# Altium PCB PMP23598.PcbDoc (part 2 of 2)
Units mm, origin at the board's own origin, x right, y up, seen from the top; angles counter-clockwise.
Board outline 80 x 60 mm, 4 copper layers (Top Layer, Layer 1, Layer 2, Bottom Layer), stack 1.856 mm thick; 92 components, 46 nets, 417 pads, 121 vias.
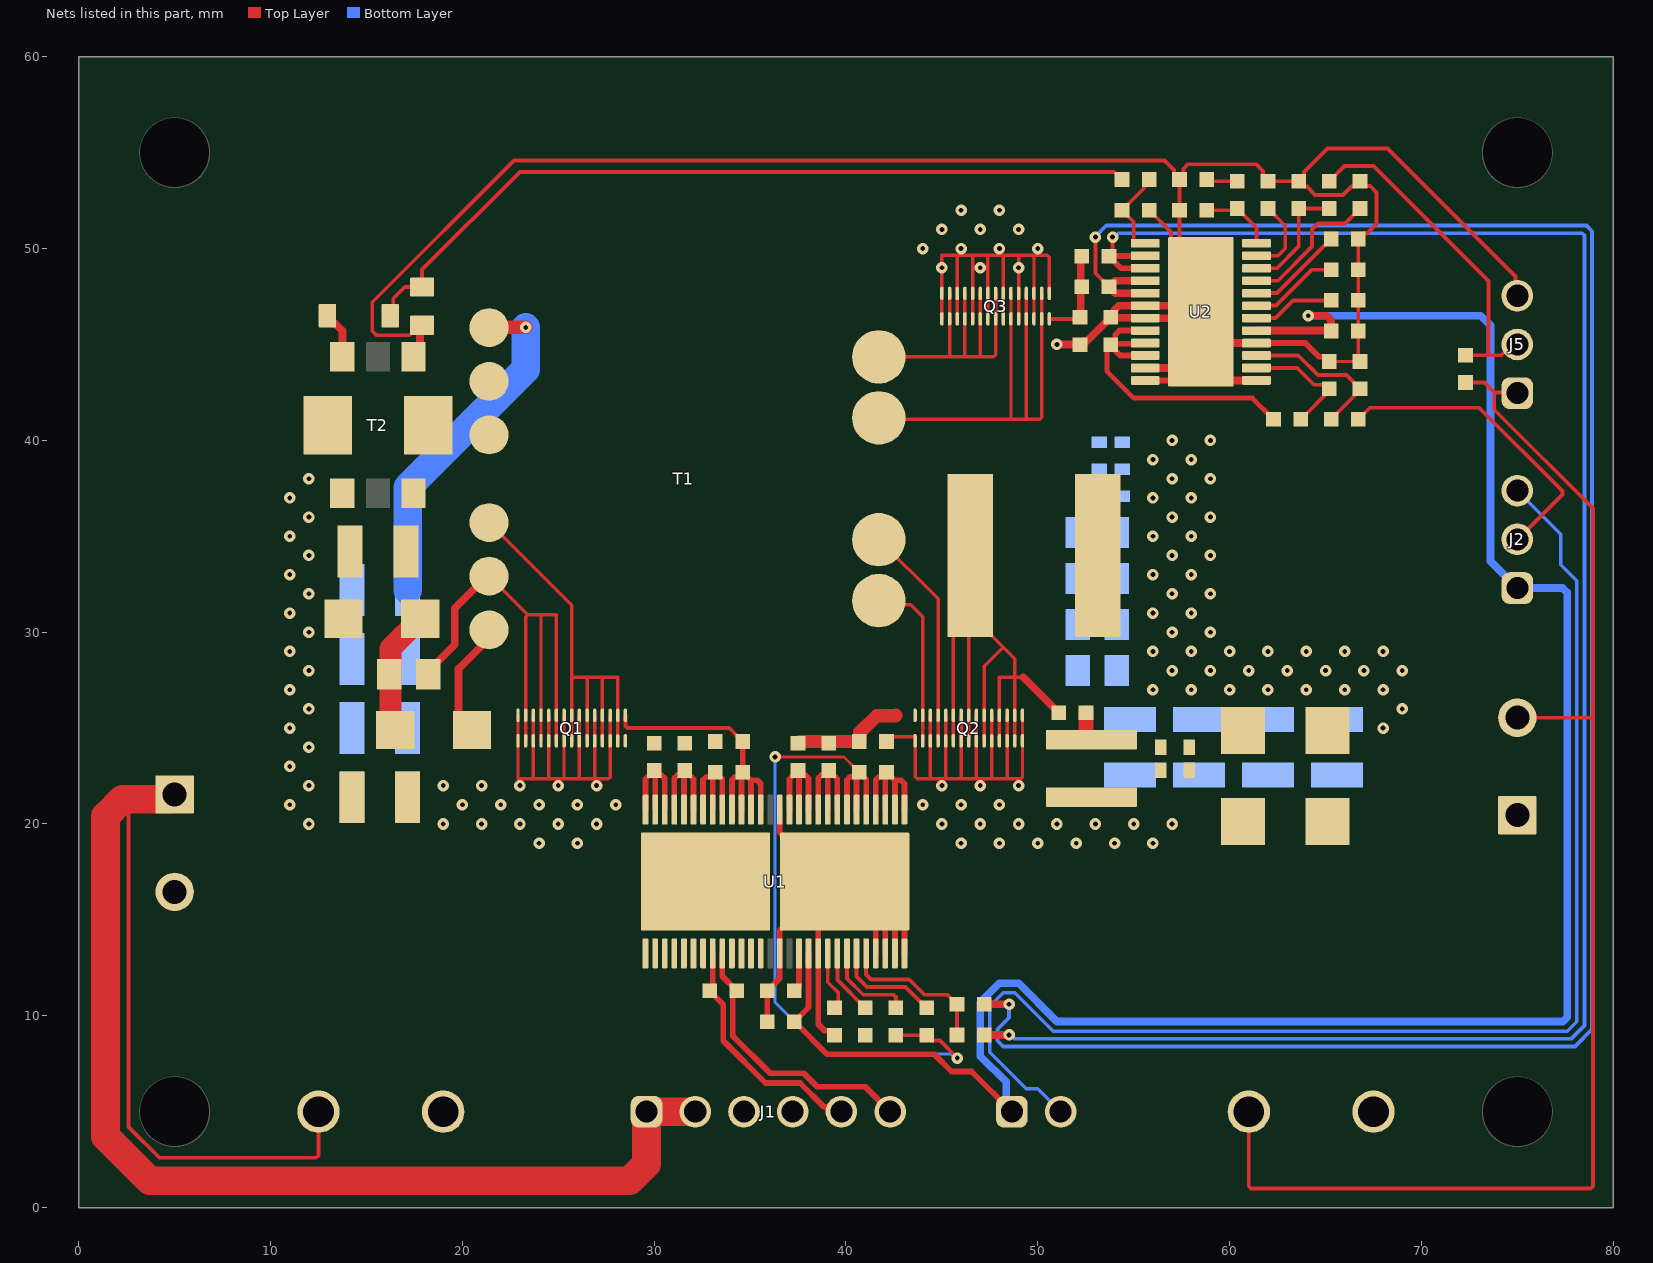
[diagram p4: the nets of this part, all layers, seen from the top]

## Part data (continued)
TP2 TP4: library part CMP-0055148-2, "Test Point, Multipurpose, Black, TH", Color=Black, Manufacturer="Keystone Electronics", Supplier Part Number 1=36-5011-ND
U1: library part CMP-0120202-4, Manufacturer="Texas Instruments", Operating Temperature Range=to
U2: library part CMP-0122233-2, "Radiation-Hardness-Assured 1-MHz Current Mode PWM Controller with Integrated Gate Driver", Manufacturer="Texas Instruments", Max Supply Voltage=14V, Min Supply Voltage=4.5V, Nominal Supply Current=5-22mA, Operating Temperature Range="-55°C to +125°C"

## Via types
v1: diameter 0.6, hole 0.25, Top Layer to Bottom Layer, 121 vias

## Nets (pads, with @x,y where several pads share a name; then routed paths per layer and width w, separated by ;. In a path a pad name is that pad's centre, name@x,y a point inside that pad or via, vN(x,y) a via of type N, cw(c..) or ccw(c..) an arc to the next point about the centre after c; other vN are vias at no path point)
+12Vp: C10.1 J1.5 U1.8 | length 12.6
  Top Layer w0.3: U1.8@33.05,13.25 33.05,11.461 C10.1@32.889,11.3 33.6,10.589 33.6,8.7 35.8,6.5 37.6,6.5 38.842,5.258 39.502,5.258 J1.5@39.76,5
+12Vs: C1.1 C2.1 J2.1 J3.1 U1.18 U2.17 | length 110
  Top Layer w0.3: U1.18@38.05,13.25 38.05,10.439 C1.1@37.311,9.7 39.011,8 44.6,8 45.5,7.1 46.55,7.1 J3.1@48.65,5
  Top Layer w0.4: U2.17@61.4,45.725 C2.1@65.264,45.725 ; v1(64.1,46.5) 65.054,46.5 65.289,46.266 C2.1@65.289,45.7
  Bottom Layer w0.4: J3.1@48.65,5 48.347,5.303 48.347,6.553 47,7.9 47,10.7 48,11.7 49,11.7 51,9.7 77.366,9.7 77.6,9.934 77.6,32.066 77.366,32.3 J2.1@75,32.3 73.6,33.7 73.6,46 73.1,46.5 v1(64.1,46.5)
BP5L: C8.2 R5.2 R8.1 U1.33 U1.34 U1.35 | length 37.8
  Top Layer w0.152: v1(36.3,23.5) 39.889,23.5 C8.2@40.689,22.7
  Top Layer w0.2: R8.1@42.6,8.989 R5.2@44.2,8.989 44.481,8.708 44.892,8.708 v1(45.8,7.8)
  Top Layer w0.3: U1.35@40.05,20.75 40.05,22.293 40.226,22.469 C8.2@40.458,22.469 ; U1.34@40.55,20.75 C8.2@40.55,22.561 ; C8.2@40.689,22.7 41.05,22.339 U1.33@41.05,20.75
  Bottom Layer w0.152: v1(36.3,23.5) 36.3,10.711 39.011,8 45.482,8 45.682,7.8 v1(45.8,7.8)
CS: D3.1 R18.2 R30.2 | length 42.4
  Top Layer w0.2: D3.1@16.235,46.5 16.393,46.658 16.393,47.393 16.992,47.992 17.892,47.992 R30.2@17.9,48 17.9,48.9 23,54 53.989,54 R18.2@54.389,53.6
NetC3_2: C3.2 U1.17 | length 2
  Top Layer w0.2: C3.2@37.311,11.3 C3.2@37.55,11.539
  Top Layer w0.3: C3.2@37.55,11.539 U1.17@37.55,13.25
NetC4_1: C4.1 R1.2 U2.8 U2.9 U2.10 | length 17.4
  Top Layer w0.254: C4.1@53.8,44.989 53.6,44.789 53.6,43.6 55,42.2 61.189,42.2 R1.2@62.289,41.1
  Top Layer w0.3: U2.10@55.6,44.425 54.3,44.425 54.031,44.694 54.031,44.758 C4.1@53.8,44.989 ; U2.9@55.6,45.075 55.557,45.032 53.843,45.032 C4.1@53.8,44.989 ; U2.8@55.6,45.725 54.261,45.725 54.031,45.495 54.031,45.22 C4.1@53.8,44.989
NetC5_2: C5.2 U2.21 | length 7.5
  Top Layer w0.2: U2.21@61.4,48.325 62.525,48.325 64.3,50.1 64.3,51 64.6,51.3 66.011,51.3 C5.2@66.8,52.089
NetC6_1: C6.1 U2.20 | length 5.1
  Top Layer w0.2: U2.20@61.4,47.675 62.464,47.675 C6.1@65.289,50.5
NetC7_2: C7.2 U1.48 U1.49 U1.50 | length 5.9
  Top Layer w0.3: U1.50@32.55,20.75 32.55,22.293 32.726,22.469 C7.2@32.958,22.469 ; U1.49@33.05,20.75 C7.2@33.05,22.561 ; C7.2@33.189,22.7 33.55,22.339 U1.48@33.55,20.75
NetC9_1: C9.1 R14.2 | length 1.6
  Top Layer w0.2: C9.1@58.811,53.6 58.9,53.511 R14.2@60.4,53.511
NetC11_2: C11.2 R14.1 U2.24 | length 3.9
  Top Layer w0.2: C11.2@58.811,52 60.311,52 R14.1@60.4,52.089 61.4,51.089 U2.24@61.4,50.275
NetC15_1: C15.1 R18.1 U2.1 | length 4.7
  Top Layer w0.2: U2.1@55.6,50.275 55.125,50.275 55,50.4 55,51.389 C15.1@54.389,52 55.53,53.141 55.53,53.319 R18.1@55.811,53.6
NetC17_1: C17.1 D1.2 D2.1 | length 6.6
  Top Layer w1.143: D2.1@16.5,24.9 16.248,25.152 16.248,27.737 C17.1@16.184,27.8 16.248,27.864 16.248,29.148 D1.2@17.8,30.7
NetC17_2: C17.2 Q1.3 Q1.4 Q1.7 Q1.8 Q1.11 Q1.12 Q1.15 Q1.16 Q1.19 Q1.20 Q1.23 Q1.24 Q1.27 Q1.28 T1.4 T1.5 | length 56.1
  Top Layer w0.178: T1.5@21.39,32.92 23.41,30.9 ; T1.4@21.39,35.715 25.7,31.405 25.7,27.546 ; Q1.27@23.3,24.335 Q1.28@23.3,25.665 23.3,30.796 23.306,30.796 23.41,30.9 ; Q1.23@24.1,24.335 Q1.24@24.1,25.665 24.1,30.9 ; Q1.19@24.9,24.335 Q1.20@24.9,25.665 24.9,30.9 23.41,30.9 ; Q1.15@25.7,24.335 Q1.16@25.7,25.665 25.7,27.546 ; Q1.11@26.5,24.335 Q1.12@26.5,25.665 26.5,27.65 ; Q1.7@27.3,24.335 27.3,27.65 ; Q1.3@28.1,24.335 Q1.4@28.1,25.665 28.1,27.65 27.3,27.65 ; 25.7,27.546 25.804,27.65 26.5,27.65 ; 26.5,27.65 27.3,27.65
  Top Layer w0.4: C17.2@18.216,27.8 18.216,27.965 19.6,29.349 19.6,31.249 21.271,32.92 T1.5@21.39,32.92
NetC19_1: C19.1 L1.1 Q2.3 Q2.4 Q2.7 Q2.8 Q2.11 Q2.12 Q2.15 Q2.16 Q2.19 Q2.20 Q2.23 Q2.24 Q2.27 Q2.28 T1.7 T1.8 | length 60.2
  Top Layer w0.178: T1.7@41.71,31.65 41.936,31.424 43.372,31.424 44,30.796 Q2.3@44,25.665 Q2.4@44,24.335 ; T1.8@41.71,34.825 44.8,31.735 Q2.7@44.8,25.665 Q2.8@44.8,24.335 ; Q2.12@45.6,24.335 L1.1@45.6,30.9 ; Q2.16@46.4,24.335 Q2.15@46.4,25.665 46.4,33.925 L1.1@46.475,34 46.475,30.94 48.2,29.215 ; Q2.20@47.2,24.335 Q2.19@47.2,25.665 47.2,28.215 48.2,29.215 ; Q2.24@48,24.335 Q2.23@48,25.665 48,27.65 49.239,27.65 ; Q2.28@48.8,24.335 Q2.27@48.8,25.665 48.8,28.615 48.2,29.215
  Top Layer w0.4: 49.239,27.65 C19.1@51.089,25.8
NetC19_2: C19.2 R29.2 | length 1.6
  Top Layer w0.762: C19.2@52.511,25.8 52.511,24.526 52.638,24.399 R29.2@52.8,24.399
NetD2_2: D2.2 T1.6 | length 6.2
  Top Layer w0.4: D2.2@20.5,24.9 19.8,25.6 19.8,28.094 21.39,29.684 T1.6@21.39,30.125
NetD3_2: D3.2 T2.3 | length 2.6
  Top Layer w0.4: D3.2@12.965,46.5 12.965,46.345 13.22,46.09 13.374,46.09 13.746,45.718 T2.3@13.746,44.356
NetJ2_2: J2.2 R3.2 | length 16.2
  Top Layer w0.2: R3.2@66.711,41.1 67.311,41.7 73,41.7 77.347,37.353 77.347,37.187 J2.2@75,34.84
NetJ5_2: J5.2 R22.2 R25.1 | length 17.9
  Top Layer w0.2: R22.2@65.2,53.511 65.989,54.3 67.5,54.3 73.5,48.3 73.5,44.441 ; R25.1@72.3,44.441 73.5,44.441 ; J5.2@75,45 74.717,45 74.158,44.441 73.5,44.441
NetQ1_1: Q1.1 R15.2 R16.2 R17.1
NetQ2_1: Q2.1 R20.2 R21.2 R24.1 | length 6
  Top Layer w0.7: R21.2@37.5,24.211 37.589,24.3 39.1,24.3 R24.1@40.689,24.3 40.72,24.331 40.72,24.772 41.598,25.65 42.585,25.65 42.6,25.665
NetQ3_1: Q3.1 R26.1 R27.1 R28.2 | length 4.9
  Top Layer w0.2: Q3.1@50.6,46.335 52.124,46.335 R28.2@52.2,46.411
  Top Layer w0.4: R28.2@52.2,46.411 52.244,46.456 52.244,49.556 R26.1@52.289,49.6
NetQ3_3: Q3.3 Q3.4 Q3.7 Q3.8 Q3.11 Q3.12 Q3.15 Q3.16 Q3.19 Q3.20 Q3.23 Q3.24 Q3.27 Q3.28 T1.10 T1.11 | length 47.4
  Top Layer w0.178: T1.10@41.71,41.175 41.785,41.1 48.6,41.1 ; T1.11@41.71,44.35 45.4,44.35 ; Q3.28@45.4,47.665 45.4,44.35 ; Q3.24@46.2,47.665 Q3.23@46.2,46.335 46.2,44.35 ; Q3.20@47,47.665 Q3.19@47,46.335 47,44.35 ; Q3.16@47.8,47.665 Q3.15@47.8,46.335 47.8,44.454 47.696,44.35 47,44.35 ; Q3.12@48.6,47.665 48.6,41.1 ; Q3.8@49.4,47.665 Q3.7@49.4,46.335 49.4,41.1 ; Q3.4@50.2,47.665 Q3.3@50.2,46.335 50.2,41.204 50.096,41.1 49.4,41.1 ; 45.4,44.35 46.2,44.35 ; 46.2,44.35 47,44.35 ; 48.6,41.1 49.4,41.1
NetR1_1: R1.1 R2.1 U2.14 | length 6.5
  Top Layer w0.2: U2.14@61.4,43.775 63.525,43.775 64.397,42.903 64.986,42.903 R2.1@65.2,42.689 64.919,42.408 64.919,42.308 63.992,41.381 R1.1@63.711,41.1
NetR3_1: R3.1 R9.2 U2.15 | length 8.3
  Top Layer w0.2: U2.15@61.4,44.425 63.575,44.425 64.6,43.4 66.089,43.4 R9.2@66.8,42.689 66.519,42.408 66.519,42.33 R3.1@65.289,41.1
NetR4_2: R4.2 U1.21 | length 3.4
  Top Layer w0.2: U1.21@39.55,13.25 39.55,11.861 R4.2@41,10.411
NetR5_1: R5.1 U1.23 | length 5.5
  Top Layer w0.2: U1.23@40.55,13.25 40.55,12.05 41.1,11.5 43.111,11.5 R5.1@44.2,10.411
NetR6_1: R6.1 R7.1 U1.24 | length 8.1
  Top Layer w0.2: U1.24@41.05,13.25 41.05,12.15 41.3,11.9 43.3,11.9 44.1,11.1 45.289,11.1 R7.1@45.789,10.6 R6.1@45.789,9
NetR8_2: R8.2 U1.22 | length 4.8
  Top Layer w0.2: U1.22@40.05,13.25 40.05,11.95 40.9,11.1 42.483,11.1 42.6,10.983 R8.2@42.6,10.411
NetR10_2: R10.2 U1.20 | length 3.1
  Top Layer w0.2: U1.20@39.05,13.25 39.05,11.75 39.6,11.2 39.6,10.611 R10.2@39.4,10.411
NetR11_2: R11.2 U2.18 | length 4.3
  Top Layer w0.2: U2.18@61.4,46.375 62.385,46.375 63.31,47.3 R11.2@65.289,47.3
NetR12_2: R12.2 U2.19 | length 4.7
  Top Layer w0.2: U2.19@61.4,47.025 62.425,47.025 64.3,48.9 R12.2@65.289,48.9
NetR13_2: R13.2 U2.23 | length 4.1
  Top Layer w0.2: U2.23@61.4,49.625 62.525,49.625 62.9,50 62.9,51.189 R13.2@62,52.089
NetR15_1: R15.1 U1.51 U1.52 U1.53 | length 6.5
  Top Layer w0.3: U1.53@31.05,20.75 31.05,22.382 31.226,22.558 31.369,22.558 31.55,22.739 U1.52@31.55,20.75 ; R15.1@31.6,22.789 32.05,22.339 U1.51@32.05,20.75
NetR16_1: R16.1 U1.54 U1.55 U1.56 | length 6.6
  Top Layer w0.3: U1.56@29.55,20.75 29.55,22.339 R16.1@30,22.789 ; U1.55@30.05,20.75 30.05,22.739 R16.1@30,22.789 ; U1.54@30.55,20.75 30.55,22.382 30.374,22.558 30.231,22.558 R16.1@30,22.789
NetR19_2: R19.2 R22.1 U2.22 | length 6.3
  Top Layer w0.2: U2.22@61.4,48.975 62.475,48.975 63.6,50.1 R19.2@63.6,52.089 R22.1@65.2,52.089
NetR20_1: R20.1 U1.36 U1.37 U1.38 | length 6.5
  Top Layer w0.3: U1.38@38.55,20.75 38.55,22.382 38.726,22.558 38.869,22.558 39.05,22.739 U1.37@39.05,20.75 ; R20.1@39.1,22.789 39.55,22.339 U1.36@39.55,20.75
NetR21_1: R21.1 U1.39 U1.40 U1.41 | length 6.6
  Top Layer w0.3: U1.41@37.05,20.75 37.05,22.339 R21.1@37.5,22.789 ; U1.40@37.55,20.75 37.55,22.739 R21.1@37.5,22.789 ; U1.39@38.05,20.75 38.05,22.382 37.874,22.558 37.731,22.558 R21.1@37.5,22.789
NetR23_1: R23.1 T1.2 T1.3 T2.6 T2.8
OUTH: R6.2 R26.2 U2.2 U2.3 | length 102.7
  Top Layer w0.2: R26.2@53.711,49.6 53.9,49.789 v1(53.9,50.6)
  Top Layer w0.3: U2.3@55.6,48.975 54.336,48.975 R26.2@53.711,49.6 53.724,49.612 55.587,49.612 U2.2@55.6,49.625
  Top Layer w0.4: R6.2@47.211,9 v1(48.5,9)
  Bottom Layer w0.2: v1(48.5,9) 48.611,9 48.811,8.8 77.8,8.8 78.5,9.5 78.5,50.683 78.383,50.8 54.211,50.8 54.011,50.6 v1(53.9,50.6)
OUTL: R7.2 R27.2 U2.4 U2.5 | length 109.8
  Top Layer w0.2: v1(53,50.6) 53,48.711 R27.2@53.711,48
  Top Layer w0.4: R7.2@47.211,10.6 v1(48.5,10.6) ; U2.5@55.6,47.675 54.036,47.675 R27.2@53.711,48 54.036,48.325 U2.4@55.6,48.325
  Bottom Layer w0.2: v1(48.5,10.6) 48.5,9.9 47.9,9.3 47.9,8.7 48.2,8.4 78,8.4 78.9,9.3 78.9,50.9 78.6,51.2 53.571,51.2 53,50.629 v1(53,50.6)
PGND: C7.1 C10.2 C12.2 C13.2 C14.2 C16.2 C18.2 J1.3 J1.4 J1.6 J4.2 Q1. Q1.2 Q1.5 Q1.6 Q1.9 Q1.10 Q1.13 Q1.14 Q1.17 Q1.18 Q1.21 Q1.22 Q1.25 Q1.26 Q1.30 R17.2 T1.1 TP2.1 U1.1 U1.2 U1.3 U1.4 U1.5 U1.6 U1.7 U1.9 U1.10 U1.11 U1.12 U1.13 U1.44 U1.45 U1.46 U1.47 U1.57 | length 77.5
  Top Layer w0.178: Q1.30@22.9,25.665 22.9,22.35 27.615,22.35 27.7,22.435 Q1.5@27.7,24.335 Q1.6@27.7,25.665 ; 23.7,22.35 Q1.25@23.7,24.335 Q1.26@23.7,25.665 ; 24.5,22.35 Q1.21@24.5,24.335 Q1.22@24.5,25.665 ; 25.3,22.454 Q1.17@25.3,24.335 Q1.18@25.3,25.665 ; 26.1,22.35 Q1.14@26.1,25.665 ; 26.9,22.35 Q1.9@26.9,24.335 Q1.10@26.9,25.665
  Top Layer w0.2: Q1.2@28.5,25.665 28.5,25.117 28.617,25 33.911,25 R17.2@34.611,24.3
  Top Layer w0.3: U1.9@33.55,13.25 33.55,12.061 C10.2@34.311,11.3 34.1,11.089 34.1,8.95 36.05,7 37.8,7 38.5,6.3 41,6.3 J1.6@42.3,5 ; U1.47@34.05,20.75 34.05,22.293 34.226,22.469 34.38,22.469 C7.1@34.611,22.7 ; U1.46@34.55,20.75 34.55,22.639 C7.1@34.611,22.7 ; R17.2@34.611,24.3 C7.1@34.611,22.7 ; U1.45@35.05,20.75 35.05,22.261 ; U1.44@35.55,20.75 35.55,22.1 35.374,22.276 35.126,22.276 35.111,22.261 35.05,22.261 ; C7.1@34.611,22.7 35.05,22.261
  Top Layer w0.7: T1.1@21.39,45.875 21.405,45.89 v1(23.3,45.89)
  Bottom Layer w1.5: C18.2@17.15,32.2 17.15,37.55 23.3,43.7 v1(23.3,45.89)
  other v1: 24,19 26,19 19,20 21,20 23,20 25,20 27,20 20,21 22,21 24,21 26,21 28,21 19,22 21,22 23,22 25,22 27,22
SGND: C1.2 C2.2 C3.1 C4.2 C5.1 C6.2 C8.1 C9.2 C11.1 C15.2 C20.1 C21.2 C22.1 C23.2 C24.1 C25.2 C26.1 C27.2 C28.2 C29.2 C30.2 C31.2 C32.2 C33.2 C34.2 J2.3 J3.2 J5.3 J6.1 Q2.2 Q2.5 Q2.6 Q2.9 Q2.10 Q2.13 Q2.14 Q2.17 Q2.18 Q2.21 Q2.22 Q2.25 Q2.26 Q2.29 Q2.30 Q3.2 Q3.5 Q3.6 Q3.9 Q3.10 Q3.13 Q3.14 Q3.17 Q3.18 Q3.21 Q3.22 Q3.25 Q3.26 Q3.29 Q3.30 R2.2 R4.1 R9.1 R10.1 R11.1 R12.1 R13.1 R19.1 R24.2 R28.1 R29.1 R30.1 T2.1 TP4.1 U1.15 U1.19 U1.25 U1.26 U1.27 U1.28 U1.29 U1.30 U1.31 U1.32 U1.42 U1.58 U2.6 U2.7 U2.11 U2.12 U2.13 U2.16 U2.25 | length 294.1
  Top Layer w0.178: R24.2@42.111,24.3 42.351,24.539 43.599,24.539 43.6,24.538 43.6,22.454 43.704,22.35 44.4,22.35 ; Q2.5@44.4,25.665 Q2.6@44.4,24.335 44.4,22.35 ; Q3.29@45,46.335 45,49.65 45.8,49.65 ; Q2.9@45.2,25.665 Q2.10@45.2,24.335 45.2,22.35 ; Q3.25@45.8,46.335 Q3.26@45.8,47.665 45.8,49.65 ; Q2.13@46,25.665 Q2.14@46,24.335 46,22.35 ; Q3.21@46.6,46.335 46.6,49.65 ; 46.8,22.454 Q2.17@46.8,25.665 ; Q3.17@47.4,46.335 47.4,49.546 ; Q2.21@47.6,25.665 47.6,22.35 ; Q3.13@48.2,46.335 Q3.14@48.2,47.665 48.2,49.65 ; Q2.25@48.4,25.665 Q2.26@48.4,24.335 48.4,22.35 ; Q3.9@49,46.335 Q3.10@49,47.665 49,49.65 ; Q2.29@49.2,25.665 49.2,22.435 49.115,22.35 48.4,22.35 ; Q3.5@49.8,46.335 Q3.6@49.8,47.665 49.8,49.65 ; Q3.2@50.6,47.665 50.6,49.546 50.496,49.65 49.8,49.65 ; R2.2@64.953,44.358 R2.2@65.2,44.111 R9.1@66.711,44.111 ; C6.2@66.711,50.5 C2.2@66.711,45.7 66.711,44.2 R9.1@66.8,44.111 ; 44.4,22.35 45.2,22.35 ; 45.2,22.35 46,22.35 ; 45.8,49.65 46.6,49.65 ; 46,22.35 47.6,22.35 ; 46.6,49.65 48.2,49.65 ; 47.6,22.35 48.4,22.35 ; 48.2,49.65 49,49.65 ; 49,49.65 49.8,49.65
  Top Layer w0.2: R30.1@17.79,45.89 17.665,45.89 17.257,45.482 15.518,45.482 15.3,45.7 15.3,47.2 22.7,54.6 56.6,54.6 57.108,54.092 57.108,53.881 C9.2@57.389,53.6 ; C15.2@55.811,52 56.94,50.871 56.94,50.511 57.151,50.3 57.3,50.3 57.389,50.389 C11.1@57.389,52 C9.2@57.389,53.6 ; C6.2@66.711,50.5 66.992,50.781 67.162,50.781 67.664,51.283 67.664,52.918 67.329,53.253 67.058,53.253 C5.1@66.8,53.511 66.519,53.23 66.35,53.23 65.92,52.8 64.457,52.8 64.027,53.23 63.881,53.23 R19.1@63.6,53.511 ; J5.3@75,47.54 74.897,47.643 74.897,48.548 68.227,55.218 65.104,55.218 63.881,53.995 63.881,53.792 R19.1@63.6,53.511 ; C9.2@57.389,53.6 57.597,53.808 57.597,54.164 57.833,54.4 61.371,54.4 61.737,54.034 61.737,53.775 R13.1@62,53.511 R19.1@63.6,53.511
  Top Layer w0.3: C1.2@35.889,9.7 C3.1@35.889,11.3 36.55,11.961 U1.15@36.55,13.25 36.55,14.45 37.4,15.3 U1.58@37.4,16.35 ; U1.42@36.55,20.75 36.55,19.55 37.15,18.95 U1.58@37.4,18.95 ; U1.58@38.5,15.05 38.55,15 U1.19@38.55,13.25 38.55,9.564 38.894,9.22 39.169,9.22 R10.1@39.4,8.989 ; U1.58@40.7,16.35 41.55,15.5 U1.25@41.55,13.25 ; U1.32@41.55,20.75 41.55,22.293 41.726,22.469 41.88,22.469 C8.1@42.111,22.7 ; U1.26@42.05,13.25 42.05,16.1 42.55,15.6 U1.27@42.55,13.25 ; U1.31@42.05,20.75 42.05,22.639 C8.1@42.111,22.7 ; U1.30@42.55,20.75 42.55,22.261 ; U1.58@42.9,15.05 43.05,14.9 U1.28@43.05,13.25 ; U1.29@43.05,20.75 43.05,22.1 42.874,22.276 42.626,22.276 42.611,22.261 42.55,22.261 ; U2.12@55.6,43.125 58.002,43.125 U2.25@58.04,43.163 ; U2.16@61.4,45.075 63.947,45.075 64.663,44.358 R2.2@64.953,44.358 ; C8.1@42.111,22.7 42.55,22.261
  Top Layer w0.4: T2.1@17.454,44.356 17.79,44.692 R30.1@17.79,45.89 ; v1(51,45) 51.006,44.994 52.194,44.994 R28.1@52.2,44.989 52.381,45.17 52.559,45.17 C4.2@53.8,46.411 53.981,46.592 53.981,46.791 54.215,47.025 U2.6@55.6,47.025 58.175,47.025 U2.25@58.5,46.7 ; C4.2@53.981,46.393 55.582,46.393 U2.7@55.6,46.375 58.455,46.375 U2.25@58.575,46.256 ; U2.11@55.6,43.775 57,43.775 58.5,45.275 58.5,44.625 60,43.125 U2.13@61.4,43.125 ; U2.25@58.697,46.378 60,45.075 U2.16@61.4,45.075
  Bottom Layer w0.178: J3.2@51.19,5 49.99,6.2 49.4,6.2 47.5,8.1 47.5,10.5 48.2,11.2 48.8,11.2 50.8,9.2 77.6,9.2 78.1,9.7 78.1,32.673 77.267,33.505 77.267,35.113 J2.3@75,37.38
  other v1: 46,19 48,19 50,19 52,19 54,19 56,19 45,20 47,20 49,20 51,20 53,20 55,20 57,20 44,21 46,21 48,21 45,22 47,22 49,22 45,49 47,49 49,49 44,50 46,50 48,50 50,50 45,51 47,51 49,51 46,52 48,52
VIN: C12.1 C13.1 C14.1 C16.1 C18.1 D1.1 J1.1 J1.2 J4.1 R23.2 T2.4 T2.7 TP1.1 | length 85.8
  Top Layer w0.2: 2.6,21.54 2.6,4.2 4.2,2.6 12.383,2.6 12.5,2.717 TP1.1@12.5,5
  Top Layer w1.5: J4.1@5,21.54 4.75,21.29 2.279,21.29 1.4,20.411 1.4,3.7 3.7,1.4 28.721,1.4 29.6,2.279 J1.1@29.6,5 J1.2@32.14,5
  other v1: 12,20 11,21 12,22 11,23 12,24 11,25 12,26 11,27 12,28 11,29 12,30 11,31 12,32 11,33 12,34 11,35 12,36 11,37 12,38
VOUT: C20.2 C21.1 C22.2 C23.1 C24.2 C25.1 C26.2 C27.1 C28.1 C29.1 C30.1 C31.1 C32.1 C33.1 C34.1 J5.1 J6.2 L1.2 R25.2 TP3.1 | length 72.3
  Top Layer w0.2: TP3.1@61,5 61,1.117 61.117,1 78.824,1 78.941,1.117 78.941,25.54 ; R25.2@72.3,43.019 73.281,43.019 73.8,42.5 ; J6.2@75,25.54 78.941,25.54 ; J5.1@75,42.46 74.96,42.5 73.8,42.5 ; 73.8,42.5 73.8,41.6 78.941,36.459 78.941,25.54
  other v1: 68,25 69,26 56,27 58,27 60,27 62,27 64,27 66,27 68,27 57,28 59,28 61,28 63,28 65,28 67,28 69,28 56,29 58,29 60,29 62,29 64,29 66,29 68,29 57,30 59,30 56,31 58,31 57,32 59,32 56,33 58,33 57,34 59,34 56,35 58,35 57,36 59,36 56,37 58,37 57,38 59,38 56,39 58,39 57,40 59,40
pads on no net: H1.0 H1.MH H2.0 H2.MH H3.0 H3.MH H4.0 H4.MH Q2. Q3. T2.2 T2.5 U1.14 U1.16 U1.43

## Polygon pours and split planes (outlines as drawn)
VOUT on Top Layer "TOP_LAYER_VOUT_P000" (solid, remove dead copper, pour order 0): 50.8,45 50.8,39.6 51.6,38.8 51.6,27.2 55.156,23.644 78.5,23.644 78.5,36.2 73.6,41.1 62.289,41.1 61.189,42.2 55,42.2 53.6,43.6 53.6,45
SGND on Top Layer "TOP_LAYER_SGND_P009" (solid, remove dead copper, pour order 9): 50,0 50,5.6 47.6,8 39.011,8 37.311,9.7 37.311,23.889 37.3,23.9 79,23.9 79,1.176 62.6,1.198 62.6,5 59.4,5 59.4,0
SGND on Top Layer "TOP_LAYER_SGND_P008" (solid, remove dead copper, pour order 8): 0,60 0,43.6 18.1,43.6 18.1,49.9 22.7,54.5 40.1,54.5 40.1,47.418 41.518,46 53.5,46 53.5,44.425 62.335,44.425 65.66,41.1 73.6,41.1 73.6,46.6 80,46.6 80,60
PGND on Top Layer "TOP_LAYER_PGND_P006" (solid, remove dead copper, pour order 6): 0.602,23.6 29.2,23.6 29.2,21 36.1,21 36.1,14.4 33.3,14.4 33.3,9.75 36.212,6.838 38.2,6.838 38.2,4.113 33.487,4.113 33.5,5 28.3,5 28.3,1.4 0.647,1.4
NetC19_1 on Top Layer "TOP_LAYER_NETC19_1_P005" (solid, remove dead copper, pour order 5): 41,39 40.1,38.1 40.1,29.2 43,26.3 50.6,26.3 50.6,27.4 48,30 48,38.4 47.4,39
NetQ3_3 on Top Layer "TOP_LAYER_NETQ3_3_P004" (solid, remove dead copper, pour order 4): 41,46 40.1,45.1 40.1,40.5 41,39.6 49.8,39.6 50.3,40.1 50.3,46
VIN on Top Layer "TOP_LAYER_VIN_P003" (solid, remove dead copper, pour order 3): 15.2,43.1 15.2,19.2 0,19.2 0,43.1
NetR23_1 on Top Layer "TOP_LAYER_NETR23_1_P002" (solid, remove dead copper, pour order 2): 16.4,32.6 16.814,32.186 19.086,32.186 20.015,33.115 20.015,36.515 20.5,37 23.5,37 24.4,37.9 24.4,44 24.05,44.35 18.85,44.35 16.4,41.9
NetC17_2 on Top Layer "TOP_LAYER_NETC17_2_P001" (solid, remove dead copper, pour order 1): 20.015,36.515 20.5,37 24.02,37 29,32.02 29,25 22.9,25 22.9,30 21.25,31.65 20.015,31.65
SGND on Bottom Layer "BOTTOM_LAYER_SGND_P018" (solid, remove dead copper, pour order 18): 80,8.1 38.911,8.1 36.1,10.911 36.1,27 36.6,27.5 39.7,27.5 40.3,28.1 40.3,48.215 40,48.515 39.985,48.5 21.5,48.5 18.5,45.5 18.5,44.1 18,43.6 0,43.6 0,60 80,60
PGND on Bottom Layer "BOTTOM_LAYER_PGND_P015" (solid, remove dead copper, pour order 15): 0,0 0,19.2 15.2,19.2 15.2,43.1 22.2,43.1 22.7,42.6 22.7,28.1 23.3,27.5 34.8,27.5 35.3,27 35.3,7 35.8,6.5 43.2,6.5 43.7,6 43.7,0
VIN on Bottom Layer "BOTTOM_LAYER_VIN_P014" (solid, remove dead copper, pour order 14): 15.2,43.1 15.2,19.2 0,19.2 0,43.1
VOUT on Bottom Layer "BOTTOM_LAYER_VOUT_P007" (solid, remove dead copper, pour order 7): 53.2,39.8 53.2,24.7 53.9,24 77,24 77,31 75,31 75,41.1 54.5,41.1
SGND on Layer 1 "LAYER_1_SGND_P020" (solid, remove dead copper, pour order 20): 80,0 45,0 45,6.2 43.7,7.5 36.85,7.5 36.1,8.25 36.1,27 36.6,27.5 39.7,27.5 40.3,28.1 40.3,48.215 40,48.515 39.985,48.5 21.5,48.5 18.5,45.5 18.5,44.4 18.1,44 0,44 0,60 80,60
PGND on Layer 1 "LAYER_1_PGND_P016" (solid, remove dead copper, pour order 16): 0,0 0,19.2 15.2,19.2 15.2,43.1 22.2,43.1 22.7,42.6 22.7,28.1 23.3,27.5 34.8,27.5 35.3,27 35.3,7.35 36.15,6.5 43.2,6.5 43.7,6 43.7,0
VIN on Layer 1 "LAYER_1_VIN_P013" (solid, remove dead copper, pour order 13): 15.2,43.1 15.2,19.2 0,19.2 0,43.1
VOUT on Layer 1 "LAYER_1_VOUT_P011" (solid, remove dead copper, pour order 11): 53.2,39.8 53.2,24.7 53.9,24 77,24 77,31 73.7,31 73.7,40.4 73,41.1 54.5,41.1
SGND on Layer 2 "LAYER_2_SGND_P019" (solid, remove dead copper, pour order 19): 80,0 45,0 45,6.2 43.7,7.5 36.85,7.5 36.1,8.25 36.1,27 36.6,27.5 39.7,27.5 40.3,28.1 40.3,48.215 40,48.515 39.985,48.5 21.5,48.5 18.5,45.5 18.5,44.4 18.1,44 0,44 0,60 80,60
PGND on Layer 2 "LAYER_2_PGND_P017" (solid, remove dead copper, pour order 17): 0,0 0,19.2 15.2,19.2 15.2,43.1 22.2,43.1 22.7,42.6 22.7,28.1 23.3,27.5 34.8,27.5 35.3,27 35.3,7.35 36.15,6.5 43.2,6.5 44,5.7 44,0
VIN on Layer 2 "LAYER_2_VIN_P012" (solid, remove dead copper, pour order 12): 15.2,43.1 15.2,19.2 0,19.2 0,43.1
VOUT on Layer 2 "LAYER_2_VOUT_P010" (solid, remove dead copper, pour order 10): 53.2,39.8 53.2,24.7 53.9,24 77,24 77,31 73.7,31 73.7,40.4 73,41.1 54.5,41.1

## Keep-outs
Keep-Out Layer:
  text ".Layer_Name" at 14.656,-21.806 h1.52

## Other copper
Top Layer:
  rectangle net SGND: 41.447,12.503 42.125,14.556
  rectangle net SGND: 41.455,19 42.05,22.28
  rectangle net SGND: 50.6,47.3 51.107,48.65
  rectangle net SGND: 44.405,46.518 45,48.711
  rectangle net SGND: 49.2,23.1 49.914,26.05
  rectangle net SGND: 41.578,23.411 43.6,24.538
  rectangle net PGND: 33.9,19.145 35.7,21
  rectangle net PGND: 33.45,12.498 35.668,14.9
  rectangle net PGND: 31.725,12.189 32.675,15.05
  region net NetQ2_1: 43.6,26.03 41.8,26.03 41.8,25.3 43.6,25.3
  rectangle net NetQ1_1: 28.5,24 33.6,24.7
  pour cut-out: 75.412,30.959 78.5,30.959 78.5,34.986 76.237,34.986 76.3,38.7 74.944,38.713 73.667,37.555 73.659,37.548 73.659,31.888 75.275,31.888
  text ".Layer_Name" at 14.656,-21.806 h1.52
Bottom Layer:
  text ".Layer_Name" at 14.656,-21.806 h1.52

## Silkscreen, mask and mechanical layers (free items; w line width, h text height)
Top Overlay:
  text "PMP23598A" at 11,53.929 h2.4
  text ".Layer_Name" at 14.656,-21.806 h1.52
Bottom Overlay:
  text ".Layer_Name" at 14.656,-21.806 h1.52
Top Paste:
  text ".Layer_Name" at 14.656,-21.806 h1.52
Bottom Paste:
  text ".Layer_Name" at 14.656,-21.806 h1.52
Top Solder:
  text ".Layer_Name" at 14.656,-21.806 h1.52
  text ".Layer_Name" at 14.656,-21.806 h1.52
Bottom Solder:
  text ".Layer_Name" at 14.656,-21.806 h1.52
Drill Guide:
  text ".Layer_Name" at 14.656,-21.806 h1.52
M1 Board Outline:
  the board outline again, w0.254
  text ".Layer_Name" at 14.656,-21.806 h1.52
M2 Board Dimensions:
  rectangle: 0,-6.985 3.175,-3.81
  rectangle: 3.175,-10.16 12.7,-6.985
  lines w0.178: 0,-6.985 25.4,-6.985 ; 3.175,-10.16 3.175,-3.81 ; 6.35,-10.16 6.35,-3.81 ; 12.7,-10.16 12.7,-3.81 ; 19.05,-10.16 19.05,-3.81 ; 0,-10.16 25.4,-10.16 25.4,-3.81 0,-3.81 0,-10.16
  text ".Layer_Name" at 14.656,-21.806 h1.52
M3 3D STEP Top:
  text ".Layer_Name" at 14.656,-21.806 h1.52
M4 3D STEP Bottom:
  text ".Layer_Name" at 14.656,-21.806 h1.52
M5 Assembly Top:
  lines w0.254: -7.417,-23.626 160.223,-23.626 ; -7.417,-18.462 160.274,-18.462 ; -7.417,-13.297 -7.417,-28.791 94.31,-28.791 160.274,-28.791 160.274,-13.297 -7.404,-13.297 -7.404,-28.791 32.614,-28.791 ; 55.194,-28.791 55.194,-13.297 ; 87.376,-18.462 87.376,-13.297 ; 108.712,-18.462 108.712,-13.297 ; 124.511,-28.956 124.511,-23.804
  text "COMPONENTS MARKED 'DNP' SHOULD NOT BE POPULATED." at 29.299,-8.09 h1.52
  text "ASSEMBLY VARIANT:" at 29.286,-11.024 h1.52
  text ".VariantName" at 55.601,-11.024 h1.52
  text "PCB VIEWED FROM TOP SIDE" at -5.804,-16.654 h1.52
  text "BOARD #:" at 57.099,-16.654 h1.52
  text ".PRJ_Number" at 70.955,-16.654 h1.52
  text "REV:" at 92.405,-16.654 h1.52
  text ".PCB_Rev" at 99.809,-16.654 h1.52
  text "SVN REV:" at 113.69,-16.654 h1.52
  text ".VersionControl_RevNumber" at 126.543,-16.654 h1.52
  text "TID #:" at 57.099,-21.819 h1.52
  text ".TID" at 70.955,-21.819 h1.52
  text "PLOT NAME =" at -5.804,-27.034 h1.52
  text ".plot_File_Name" at 14.656,-27.034 h1.52
  text "GENERATED    :" at 57.15,-27.034 h1.52
  text ".Print_Date" at 79.235,-27.034 h1.52
  text ".Print_Time" at 97.752,-27.034 h1.52
  text "TEXAS INSTRUMENTS" at 129.87,-27.034 h1.52
M6 Assembly Bottom:
  lines w0.254: -7.429,-18.474 160.261,-18.474 ; -7.379,-23.639 160.261,-23.639 ; 28.334,-28.969 28.334,-23.817 ; 44.133,-18.474 44.133,-13.31 ; 65.468,-18.474 65.468,-13.31 ; 97.65,-28.804 97.65,-13.31 ; 120.231,-28.804 160.249,-28.804 160.249,-13.31 -7.429,-13.31 -7.429,-28.804 58.534,-28.804 160.261,-28.804 160.261,-13.31
  text "COMPONENTS MARKED 'DNP' SHOULD NOT BE POPULATED." at 154.991,-8.077 h1.52
  text ".VariantName" at 128.473,-11.024 h1.52
  text "ASSEMBLY VARIANT:" at 154.864,-11.024 h1.52
  text ".VersionControl_RevNumber" at 26.302,-16.667 h1.52
  text "SVN REV:" at 39.154,-16.667 h1.52
  text ".PCB_Rev" at 53.035,-16.667 h1.52
  text "REV:" at 60.439,-16.667 h1.52
  text ".PRJ_Number" at 81.89,-16.667 h1.52
  text "BOARD #:" at 95.745,-16.667 h1.52
  text "PCB VIEWED FROM BOTTOM SIDE" at 158.648,-16.667 h1.52
  text ".TID" at 81.89,-21.831 h1.52
  text "TID #:" at 95.745,-21.831 h1.52
  text "TEXAS INSTRUMENTS" at 22.974,-27.047 h1.52
  text ".Print_Time" at 55.093,-27.047 h1.52
  text ".Print_Date" at 73.609,-27.047 h1.52
  text "GENERATED    :" at 95.694,-27.047 h1.52
  text ".plot_File_Name" at 138.189,-27.047 h1.52
  text "PLOT NAME =" at 158.648,-27.047 h1.52
M9 Title Sheet:
  drawing of 57 lines, arcs and shapes, not listed
  text "1" at 18.792,204.127 h1.78
  text "2" at 82.182,204.127 h1.78
  text "3" at 145.411,204.127 h1.78
  text "4" at 209.08,204.127 h1.78
  text "5" at 272.555,204.127 h1.78
  text "6" at 336.182,204.127 h1.78
  text "A" at -10.579,175.095 h1.78
  text "A" at 365.341,175.095 h1.78
  text "B" at -10.579,114.643 h1.78
  text "B" at 365.341,114.643 h1.78
  text "C" at -10.579,54.318 h1.78
  text "C" at 365.341,54.318 h1.78
  text "PROJECT TITLE:" at 288.125,7.048 h1.14
  text ".PRJ_Title" at 289.395,3.662 h1.78
  text "DESIGNED FOR:" at 288.125,-0.597 h1.14
  text ".PRJ_Customer" at 289.395,-4.153 h1.78
  text "D" at -10.579,-5.88 h1.78
  text "D" at 365.341,-5.88 h1.78
  text "FILE NAME:" at 288.125,-8.217 h1.14
  text ".PCB_File_Name_No_Path" at 289.395,-11.265 h1.78
  text "Texas Instruments (TI) and/or its licensors do not warrant the accuracy or completeness of this specification" at 161.9,-15.376 h1.14
  text "ENGINEER:" at 288.125,-15.583 h1.14
  text "LAYOUT BY:" at 326.352,-15.583 h1.14
  text "or any information contained therein. TI and/or its licensors do not warrant that this design will meet" at 160.757,-18.237 h1.14
  text ".PRJ_Engineer" at 289.395,-19.52 h1.78
  text ".PCB_Layout" at 327.635,-19.52 h1.78
  text "the specifications, will be suitable for your application or fit for any particular purpose, or will operate in" at 160.757,-21.099 h1.14
  text ".Layer_Name" at 14.656,-21.806 h1.52
  text "ALTIUM DESIGNER VERSION:" at 326.352,-23.457 h1.14
  text "an implementation. TI and/or its licensors do not warrant that the design is production worthy. You should" at 160.757,-23.961 h1.14
  text "completely validate and test your design implementation to confirm the system functionality for your application." at 161.9,-26.822 h1.14
  text ".print_Scale" at 289.395,-26.843 h1.78
  text ".Application_BuildNumber" at 327.635,-26.843 h1.78
  text "1" at 18.792,-32.093 h1.78
  text "2" at 82.182,-32.093 h1.78
  text "3" at 145.411,-32.093 h1.78
  text "4" at 209.08,-32.093 h1.78
  text "5" at 272.555,-32.093 h1.78
  text "6" at 336.182,-32.093 h1.78
M10 Fab Notes:
  drawing of 189 lines, arcs and shapes, not listed
  text "DESIGN INFORMATION" at 314.503,161.447 h1.52
  text "MIN. TRACK WIDTH:" at 298.131,158.091 h1.52
  text "8" at 325.976,158.091 h1.52
  text "MIL" at 329.907,158.091 h1.52
  text "7.874" at 321.75,155 h1.52
  text "MIN. CLEARANCE:" at 298.131,154.938 h1.52
  text "MIL" at 329.907,154.938 h1.52
  text "MIN. VIA PAD SIZE:" at 298.131,151.785 h1.52
  text "24" at 325.214,151.785 h1.52
  text "MIL" at 329.907,151.785 h1.52
  text "0.05mm (2MIL)" at 315.784,148.486 h1.52
  text "MINIMUM ANNULAR RING" at 289.769,148.277 h1.52
  text "EXTERNAL" at 333.768,148.277 h1.52
  text "PER" at 294.849,145.48 h1.52
  text "IPC-D-275 CLASS 2 LEVEL C" at 300.437,145.48 h1.52
  text "MIL, HOLES" at 338.238,142.928 h1.52
  text "+/-" at 328.27,142.709 h1.52
  text "+/-" at 349.961,142.709 h1.52
  text "REGISTRATION TOLERANCES:" at 289.769,142.682 h1.52
  text "METAL" at 320.243,142.682 h1.52
  text "5" at 334.879,142.683 h1.52
  text "3" at 356.037,142.683 h1.52
  text "MIL" at 358.99,142.682 h1.52
  text "HOLE SIZE TOLERANCE (UNLESS OTHERWISE SPECIFIED):" at 289.769,140.185 h1.52
  text "+/-" at 349.961,140.112 h1.52
  text "3" at 356.037,140.085 h1.52
  text "MIL" at 358.99,140.085 h1.52
  text "MATERIAL:" at 287.87,136.589 h1.52
  text "FR-4 High Tg" at 312.926,133.324 h1.52
  text "X" at 309.257,133.122 h1.52
  text "FR-4" at 298.563,133.007 h1.52
  text "OTHER" at 336.358,133.007 h1.52
  text "62 MIL (1.6mm) +/-10%" at 306.694,129.374 h1.52
  text "X" at 303.643,129.312 h1.52
  text "THICKNESS:" at 289.769,129.165 h1.52
  text "OTHER" at 339.33,129.165 h1.52
  text "TOLERANCE:" at 289.769,125.652 h1.52
  text "X" at 311.314,125.652 h1.52
  text "ANSI IPC-6012 TYPE 3 CLASS 2" at 315.836,125.652 h1.52
  text "OTHER +/-" at 315.835,121.989 h1.52
  text "BOW & TWIST:" at 289.769,118.302 h1.52
  text "X" at 311.314,118.302 h1.52
  text "ANSI IPC-6012 TYPE 3 CLASS 2" at 315.836,118.302 h1.52
  text "OTHER +/-" at 315.835,114.576 h1.52
  text "DRILLING:" at 287.87,111.258 h1.52
  text "NC_DRILL FILES" at 332.599,108.586 h1.52
  text "REFERENCE:" at 289.769,108.486 h1.52
  text "X" at 306.463,108.484 h1.52
  text "AS SHOWN" at 310.984,108.486 h1.52
  text "X" at 329.348,108.486 h1.52
  text "OTHER" at 340.168,104.873 h1.52
  text "PTH COPPER THICKNESS:" at 289.761,104.783 h1.52
  text "X" at 318.697,104.783 h1.52
  text "20-30 um" at 321.948,104.783 h1.52
  text "BOARD FINISH:" at 287.87,101.034 h1.52
  text "SILKSCREEN:" at 291.812,98.237 h1.52
  text "X" at 316.14,98.237 h1.52
  text "TOP" at 319.112,98.237 h1.52
  text "X" at 329.094,98.237 h1.52
  text "BOTTOM" at 332.091,98.237 h1.52
  text "SILKSCREEN COLOR:" at 291.812,94.295 h1.52
  text "X" at 316.115,94.295 h1.52
  text "WHITE" at 319.112,94.295 h1.52
  text "OTHER" at 332.091,94.295 h1.52
  text "X" at 319.442,90.652 h1.52
  text "GREEN" at 322.439,90.652 h1.52
  text "OTHER" at 338.136,90.652 h1.52
  text "SOLDER RESIST COLOR:" at 291.812,90.477 h1.52
  text "X" at 319.442,86.734 h1.52
  text "MATTE" at 322.439,86.734 h1.52
  text "SEMI-GLOSS" at 338.125,86.717 h1.52
  text "IMMERSION GOLD (ENIG)" at 314.819,82.345 h1.52
  text "ENEPIG" at 348.793,82.162 h1.52
  text "SURFACE FINISH:" at 287.87,82.136 h1.52
  text "X" at 310.298,82.136 h1.52
  text "IMM. TIN/SILVER OR EQUIV" at 296.24,78.649 h1.52
  text "OTHER" at 332.599,78.549 h1.52
  text "ARRAY/PANEL:" at 287.87,74.602 h1.52
  text "CUT AND TRIM PER M1 BOARD OUTLINE" at 314.819,74.393 h1.52
  text "N.C. ROUTE" at 314.819,70.94 h1.52
  text "X" at 332.295,70.94 h1.52
  text "V. SCORE" at 336.816,70.94 h1.52
  text "CERTIFICATION:" at 287.87,67.66 h1.52
  text "MATERIALS AND WORKMANSHIP FOR ALL PCBS" at 306.285,67.66 h1.52
  text "TO MEET OR EXCEED THE REQUIREMENTS OF:" at 306.285,65.271 h1.52
  text "X" at 297.078,62.003 h1.52
  text "ANSI IPC-A-600F CLASS ->" at 300.329,62.003 h1.52
  text "X" at 342.188,62.003 h1.52
  text "2" at 344.982,62.003 h1.52
  text "1" at 336.981,61.965 h1.52
  text "3" at 353.973,61.965 h1.52
  text "X" at 317.702,58.252 h1.52
  text "RoHS" at 320.953,58.252 h1.52
  text "OTHER" at 337.321,58.252 h1.52
  text "PER ORDER" at 347.407,58.252 h1.52
  text "ALL BOARDS MUST MEET OR EXCEED UL94-V0 REQUIREMENTS." at 288.569,54.345 h1.52
  text "PCB MUST BEAR THE UL94V-0 UL REGISTERED MATERIAL ID NUMBER" at 288.569,51.397 h1.52
  text "ADDITIONAL REQUIREMENTS:" at 287.87,47.094 h1.52
  text "MICROSECTION:" at 289.769,44.373 h1.52
  text "YES" at 312.775,44.373 h1.52
  text "REQUIRED" at 334.657,40.707 h1.52
  text "BARE BOARD ELEC. TEST:" at 289.769,40.634 h1.52
  text "NONE" at 322.935,40.634 h1.52
  text "X" at 331.66,40.634 h1.52
  text "PER ORDER" at 349.693,40.634 h1.52
  text "XX MIL VIAS REQUIRE NON-CONDUCTIVE FILL AND PLANARIZE" at 294.04,35.428 h1.5
  text "XX MIL VIAS REQUIRE CONDUCTIVE FILL AND PLANARIZE" at 294.243,32.787 h1.52
  text "OUTER XX MIL TRACES REQUIRE 50 OHM SINGLE-ENDED IMPEDANCE" at 294.218,28.637 h1.47
  text "LAYER 2 & 3 (INNER LAYERS) XX MIL WIDE, XX MIL SPACE / TRACES REQUIRE 100 OHM DIFFERENTIAL IMPEDANCE" at 294.015,22.65 h1.52
  text ".Layer_Name" at 14.656,-21.806 h1.52
M11 Gerber Information:
  lines w0.254: -7.417,-23.626 160.223,-23.626 ; -7.417,-18.462 160.274,-18.462 ; -7.417,-13.297 -7.417,-28.791 94.31,-28.791 160.274,-28.791 160.274,-13.297 -7.404,-13.297 -7.404,-28.791 32.614,-28.791 ; 55.194,-28.791 55.194,-13.297 ; 87.376,-18.462 87.376,-13.297 ; 108.712,-18.462 108.712,-13.297 ; 124.511,-28.956 124.511,-23.804
  text "ALL ARTWORK VIEWED FROM TOP SIDE" at -5.804,-16.654 h1.52
  text "BOARD #:" at 57.099,-16.654 h1.52
  text ".PRJ_Number" at 70.955,-16.654 h1.52
  text "REV:" at 92.405,-16.654 h1.52
  text ".PCB_Rev" at 99.809,-16.654 h1.52
  text "SVN REV:" at 113.69,-16.654 h1.52
  text ".VersionControl_RevNumber" at 126.543,-16.654 h1.52
  text "LAYER NAME =" at -5.804,-21.806 h1.52
  text "TID #:" at 57.099,-21.819 h1.52
  text ".TID" at 70.955,-21.819 h1.52
  text "PLOT NAME =" at -5.804,-27.034 h1.52
  text ".plot_File_Name" at 14.656,-27.034 h1.52
  text "GENERATED    :" at 57.15,-27.034 h1.52
  text ".Print_Date" at 79.235,-27.034 h1.52
  text ".Print_Time" at 97.752,-27.034 h1.52
  text "TEXAS INSTRUMENTS" at 129.87,-27.034 h1.52
M12 Stackup:
  drawing of 295 lines, arcs and shapes, not listed
  text "Layer" at 249.469,200.023 h1.52
  text "Name" at 259.88,200.023 h1.52
  text "Material" at 283.496,200.023 h1.52
  text "Thickness" at 305.334,200.023 h1.52
  text "Constant" at 321.84,200.023 h1.52
  text "Board Layer Stack" at 336.314,200.023 h1.52
  text "Top Overlay" at 259.88,196.975 h1.52
  text "Top Solder" at 259.88,193.927 h1.52
  text "Solder Resist" at 283.496,193.927 h1.52
  text "0.40mil" at 305.334,193.927 h1.52
  text "3.5" at 321.84,193.927 h1.52
  text "1" at 249.469,190.879 h1.52
  text "Top Layer" at 259.88,190.879 h1.52
  text "2.76mil" at 305.334,190.879 h1.52
  text "Dielectric 1" at 259.88,187.831 h1.52
  text "PP-006" at 283.496,187.831 h1.52
  text "2.80mil" at 305.334,187.831 h1.52
  text "4.1" at 321.84,187.831 h1.52
  text "2" at 249.469,184.783 h1.52
  text "Layer 1" at 259.88,184.783 h1.52
  text "CF-004" at 283.496,184.783 h1.52
  text "1.38mil" at 305.334,184.783 h1.52
  text "Dielectric1" at 259.88,181.735 h1.52
  text "FR-4 High Tg" at 283.496,181.735 h1.52
  text "59.20mil" at 305.334,181.735 h1.52
  text "4.8" at 321.84,181.735 h1.52
  text "3" at 249.469,178.687 h1.52
  text "Layer 2" at 259.88,178.687 h1.52
  text "CF-004" at 283.496,178.687 h1.52
  text "1.38mil" at 305.334,178.687 h1.52
  text "Dielectric 2" at 259.88,175.639 h1.52
  text "PP-006" at 283.496,175.639 h1.52
  text "2.80mil" at 305.334,175.639 h1.52
  text "4.1" at 321.84,175.639 h1.52
  text "4" at 249.469,172.591 h1.52
  text "Bottom Layer" at 259.88,172.591 h1.52
  text "2.76mil" at 305.334,172.591 h1.52
  text "Bottom Solder" at 259.88,169.543 h1.52
  text "Solder Resist" at 283.496,169.543 h1.52
  text "0.40mil" at 305.334,169.543 h1.52
  text "3.5" at 321.84,169.543 h1.52
  text "Bottom Overlay" at 259.88,166.495 h1.52
  text ".Layer_Name" at 14.656,-21.806 h1.52
M13 Component Bodies Top:
  text ".Layer_Name" at 14.656,-21.806 h1.52
M14 Component Bodies Bottom:
  text ".Layer_Name" at 14.656,-21.806 h1.52
M15 Courtyards Top:
  text ".Layer_Name" at 14.656,-21.806 h1.52
M16 Courtyards Bottom:
  text ".Layer_Name" at 14.656,-21.806 h1.52
Drill Drawing:
  text ".Layer_Name" at 14.656,-21.806 h1.52
M17 Embedded Cavity:
  text ".Layer_Name" at 14.656,-21.806 h1.52
M18 Embedded Assembly:
  text ".Layer_Name" at 14.656,-21.806 h1.52
M19 Embedded Keepout:
  text ".Layer_Name" at 14.656,-21.806 h1.52

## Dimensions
0,-10.16 to 25.4,-10.16 on M2 Board Dimensions
0,60 to 80,0 on M2 Board Dimensions
80,0 to 0,60 on M2 Board Dimensions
